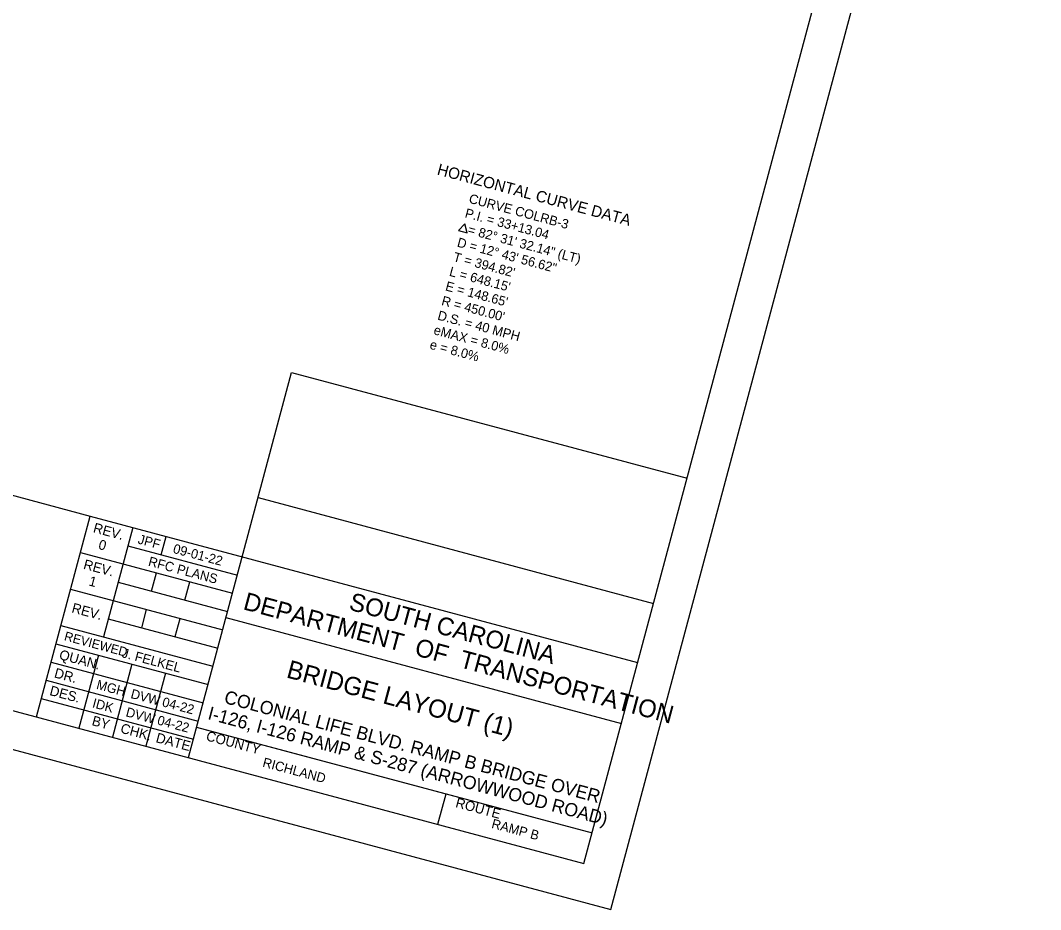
# Model space of a CAD drawing. Extents: x 1970764 to 1971371, y 795839 to 796297.
# Drawn here: x 1971168.8 to 1971371.3, y 795838.9 to 796015.4 of the extents above; entities that cross this region are included whole.
import ezdxf

# ---------------------------------------------------------------- set-up
doc = ezdxf.new("R2010")
doc.units = 0
for name, color, linetype in [('BR_BORDER LINES', 7, 'Continuous'), ('BR_TEXT', 7, 'Continuous'), ('Level 31', 7, 'Continuous')]:
    doc.layers.add(name, color=color, linetype=linetype)

msp = doc.modelspace()

# ---------------------------------------------------------------- linework, layer by layer
at = {"layer": 'BR_BORDER LINES'}
for p, q in [((1971280.7, 795848.05), (1971362.15, 796152.34)), ((1970792.88, 795978.64), (1971280.7, 795848.05)), ((1971202.21, 795869.06), (1971222.67, 795945.52)), ((1971222.67, 795945.52), (1971301.16, 795924.51)), ((1971104.94, 795937.8), (1971182.69, 795916.99)), ((1971216.03, 795920.67), (1971294.51, 795899.66)), ((1971172.02, 795877.14), (1971182.69, 795916.99)), ((1971182.69, 795916.99), (1971291.36, 795887.9)), ((1971191.14, 795914.73), (1971185.32, 795892.99)), ((1971196.81, 795909.33), (1971197.78, 795912.95)), ((1971190.17, 795911.11), (1971211.9, 795905.29)), ((1971180.75, 795909.75), (1971210.93, 795901.67)), ((1971194.87, 795902.08), (1971195.84, 795905.71)), ((1971178.81, 795902.5), (1971208.99, 795894.42)), ((1971188.23, 795903.86), (1971209.96, 795898.04)), ((1971201.51, 795900.31), (1971202.48, 795903.93)), ((1971192.93, 795894.84), (1971193.9, 795898.46)), ((1971186.29, 795896.62), (1971208.02, 795890.8)), ((1971199.57, 795893.06), (1971200.54, 795896.68)), ((1971209.64, 795896.84), (1971209.64, 795896.84)), ((1971209.64, 795896.84), (1971288.13, 795875.82)), ((1971176.87, 795895.26), (1971207.06, 795887.18)), ((1971175.9, 795891.63), (1971206.09, 795883.55)), ((1971184.35, 795889.37), (1971180.47, 795874.88)), ((1971174.93, 795888.01), (1971205.12, 795879.93)), ((1971190.99, 795887.59), (1971187.11, 795873.1)), ((1971173.96, 795884.39), (1971204.15, 795876.31)), ((1971197.63, 795885.82), (1971193.75, 795871.33)), ((1971172.99, 795880.77), (1971203.18, 795872.69)), ((1971203.82, 795875.1), (1971282.31, 795854.09)), ((1971205.24, 795874.72), (1971282.31, 795854.09)), ((1971251.72, 795855.81), (1971253.33, 795861.85))]:
    msp.add_line(p, q, dxfattribs=at)
at = {"layer": 'BR_TEXT'}
msp.add_lwpolyline([(1971257.05, 795974.99), (1971255.78, 795973.72), (1971257.52, 795973.26)], close=True, dxfattribs=at)
at = {"layer": 'Level 31'}
msp.add_line((1971247.18, 795879.95), (1971247.18, 795879.95), dxfattribs=at)
msp.add_line((1971247.18, 795879.95), (1971247.18, 795879.95), dxfattribs=at)
msp.add_lwpolyline([(1970764.38, 795978.5), (1971286.01, 795838.87), (1971371.35, 796157.64), (1970849.71, 796297.28)], close=True, dxfattribs=at)

# ---------------------------------------------------------------- texts
at = {"layer": 'BR_TEXT'}
for s, height, p in [('HORIZONTAL CURVE DATA', 2.25, (1971251.41, 795984.84)), ('CURVE COLRB-3', 1.875, (1971257.72, 795979.22)), ('P.I. = 33+13.04', 1.875, (1971256.94, 795976.32)), ('  = 82%%d 31\' 32.14" (LT)', 1.875, (1971256.16, 795973.42)), ('D = 12%%d 43\' 56.62"', 1.875, (1971255.39, 795970.52)), ("T = 394.82'", 1.875, (1971254.61, 795967.62)), ("L = 648.15'", 1.875, (1971253.84, 795964.73)), ("E = 148.65'", 1.875, (1971253.06, 795961.83)), ("R = 450.00'", 1.875, (1971252.29, 795958.93)), ('D.S. = 40 MPH', 1.875, (1971251.51, 795956.03)), ('eMAX = 8.0%', 1.875, (1971250.73, 795953.13)), ('e = 8.0%', 1.875, (1971249.96, 795950.24)), ('REV.', 1.95, (1971183.15, 795913.81)), ('JPF', 1.875, (1971192.03, 795911.58)), ('0', 1.95, (1971184.19, 795910.5)), ('09-01-22', 1.875, (1971199, 795909.71)), ('RFC PLANS', 1.875, (1971194.09, 795907.18)), ('REV.', 1.95, (1971181.21, 795906.56)), ('1', 1.95, (1971182.28, 795903.25)), ('DEPARTMENT  OF  TRANSPORTATION', 3.5381, (1971212.87, 795898.52)), ('SOUTH CAROLINA', 3.5381, (1971233.86, 795898.45)), ('REV.', 1.95, (1971178.89, 795897.91)), ('REVIEWED', 1.8, (1971177.4, 795892.37)), ('QUAN.', 1.95, (1971176.39, 795888.63)), ('J. FELKEL', 1.875, (1971188.84, 795889.01)), ('BRIDGE LAYOUT (1)', 3.6, (1971221.46, 795884.99)), ('DR.', 1.95, (1971175.42, 795884.99)), ('MGH', 1.875, (1971183.79, 795882.72)), ('DES.', 1.95, (1971174.5, 795881.49)), ('DVW', 1.875, (1971190.6, 795880.9)), ('COLONIAL LIFE BLVD. RAMP B BRIDGE OVER', 2.625, (1971209.1, 795879.92)), ('IDK', 1.875, (1971182.99, 795879.05)), ('04-22', 1.875, (1971196.84, 795879.27)), ('DVW', 1.875, (1971189.63, 795877.27)), ('I-126, I-126 RAMP & S-287 (ARROWWOOD ROAD) ', 2.625, (1971205.87, 795876.71)), ('BY', 1.95, (1971182.89, 795875.51)), ('04-22', 1.875, (1971195.87, 795875.65)), ('CHK.', 1.95, (1971188.56, 795874.01)), ('COUNTY', 1.95, (1971205.56, 795872.49)), ('DATE', 1.95, (1971195.59, 795872.13)), ('RICHLAND', 1.875, (1971216.78, 795867.28)), ('ROUTE', 1.95, (1971255.07, 795859.23)), ('RAMP B', 1.875, (1971262.22, 795855.11))]:
    msp.add_text(s, height=height, rotation=345.0137, dxfattribs=at).set_placement(p)

doc.saveas('drawing.dxf')
